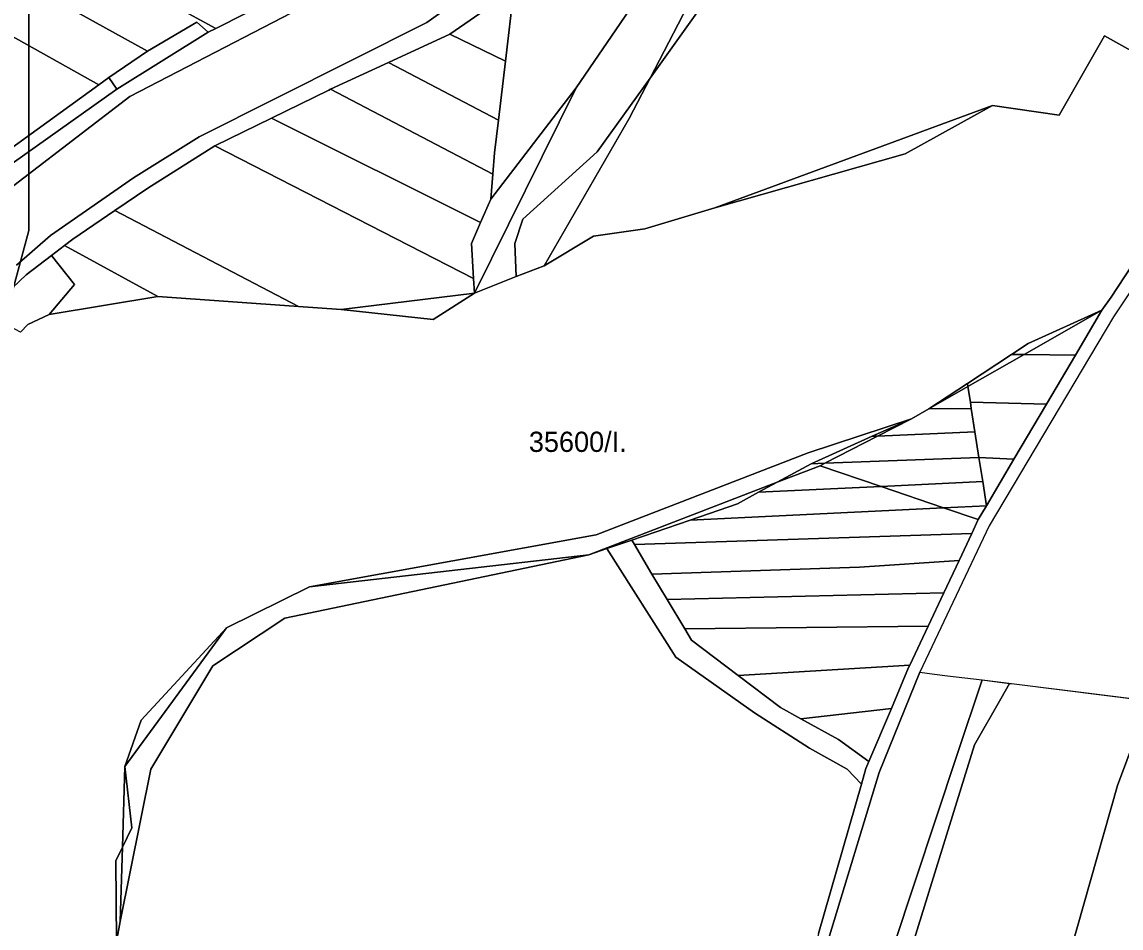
# Model space of a CAD drawing. Extents: x -537068 to -534056, y -1176840 to -1172401.
# Drawn here: x -534968.9 to -534697.4, y -1175404.2 to -1175180.5 of the extents above; entities that cross this region are included whole.
import ezdxf

# ---------------------------------------------------------------- set-up
doc = ezdxf.new("R2010")
doc.units = 0
for name, color, linetype in [('95560013', 7, 'Continuous'), ('95610013', 7, 'Continuous'), ('95630013', 7, 'Continuous'), ('95640013', 7, 'Continuous'), ('95660013', 7, 'Continuous')]:
    doc.layers.add(name, color=color, linetype=linetype)

msp = doc.modelspace()

# ---------------------------------------------------------------- linework, layer by layer
at = {"layer": '95560013'}
for points in [[(-534906.46, -1175174.67), (-534921.01, -1175182.07), (-534981.98, -1175148.9), (-535049.94, -1175112), (-535112.93, -1175078.12), (-535111.66, -1175074.89), (-535108.69, -1175067.32), (-535042.15, -1175102.18), (-534977.55, -1175137.23)], [(-535112.93, -1175078.12), (-535049.94, -1175112), (-534981.98, -1175148.9), (-534921.01, -1175182.07), (-534922.88, -1175183.02), (-534925.65, -1175180.5), (-534937.89, -1175187.69), (-535021.54, -1175141.41), (-535117.56, -1175089.94), (-535116.74, -1175087.85)], [(-535021.54, -1175141.41), (-534937.89, -1175187.69), (-534947.44, -1175194.22), (-534949.86, -1175195.98), (-535025.96, -1175153.4), (-535121.96, -1175101.18), (-535117.56, -1175089.94)], [(-535025.96, -1175153.4), (-534949.86, -1175195.98), (-534972.25, -1175212.22), (-535043.8, -1175173.13), (-535130.9, -1175126.84), (-535127.5, -1175118.23), (-535128.17, -1175112.78), (-535121.96, -1175101.18)], [(-534945.43, -1175197.06), (-534947.44, -1175194.22), (-534937.89, -1175187.69), (-534925.65, -1175180.5), (-534922.88, -1175183.02)], [(-534962.17, -1175252.75), (-534967.42, -1175255.17), (-534969.21, -1175257.08), (-534977.93, -1175252.51), (-534967.79, -1175242.94), (-534961.57, -1175238.15), (-534955.87, -1175245.29)], [(-534756.7, -1175295.18), (-534786.96, -1175296.62), (-534782.38, -1175294.15), (-534771.74, -1175290.05)], [(-534828.89, -1175312.07), (-534782.38, -1175294.15), (-534786.96, -1175296.62), (-534792.2, -1175299.46), (-534803.85, -1175303.47), (-534818.29, -1175308.43), (-534824.39, -1175310.53)], [(-534756.7, -1175295.18), (-534741.28, -1175300.44), (-534803.85, -1175303.47), (-534792.2, -1175299.46), (-534786.96, -1175296.62)], [(-534817.63, -1175309.53), (-534818.29, -1175308.43), (-534803.85, -1175303.47), (-534741.28, -1175300.44), (-534732.7, -1175303.37), (-534734.3, -1175306.78)], [(-534817.63, -1175309.53), (-534813.28, -1175316.8), (-534809.53, -1175323.06), (-534805.18, -1175330.34), (-534803.48, -1175333.17), (-534791.97, -1175341.86), (-534781.52, -1175349.75), (-534776.5, -1175352.52), (-534767.23, -1175357.62), (-534759.7, -1175363.09), (-534760.44, -1175364.83), (-534761.56, -1175368.72), (-534765.1, -1175364.97), (-534774.38, -1175359.77), (-534787.99, -1175351.11), (-534807.39, -1175337.31), (-534824.39, -1175310.53), (-534818.29, -1175308.43)], [(-534817.63, -1175309.53), (-534734.3, -1175306.78), (-534737.42, -1175313.42), (-534762.07, -1175315.14), (-534813.28, -1175316.8)], [(-534840, -1175428.9), (-534884.82, -1175421.18), (-534945.52, -1175407.54), (-534944.63, -1175402.62), (-534937.01, -1175364.95), (-534921.73, -1175339.5), (-534903.97, -1175327.66), (-534828.89, -1175312.07), (-534824.39, -1175310.53), (-534807.39, -1175337.31), (-534787.99, -1175351.11), (-534774.38, -1175359.77), (-534765.1, -1175364.97), (-534761.56, -1175368.72), (-534772.14, -1175405.55), (-534780.35, -1175439.37)], [(-534809.53, -1175323.06), (-534813.28, -1175316.8), (-534762.07, -1175315.14), (-534737.42, -1175313.42), (-534741.19, -1175321.42)], [(-534741.19, -1175321.42), (-534745.08, -1175329.69), (-534805.18, -1175330.34), (-534809.53, -1175323.06)], [(-534805.18, -1175330.34), (-534745.08, -1175329.69), (-534749.6, -1175339.29), (-534791.97, -1175341.86), (-534803.48, -1175333.17)], [(-534776.5, -1175352.52), (-534781.52, -1175349.75), (-534791.97, -1175341.86), (-534749.6, -1175339.29), (-534749.9, -1175339.92), (-534754.16, -1175349.99)], [(-534776.5, -1175352.52), (-534754.16, -1175349.99), (-534759.7, -1175363.09), (-534767.23, -1175357.62)]]:
    msp.add_lwpolyline(points, close=True, dxfattribs=at)
at = {"layer": '95610013'}
for points in [[(-534802.18, -1175178.19), (-534792.11, -1175162.32), (-534782.71, -1175140.53), (-534776.79, -1175122.8), (-534776.64, -1175118.75), (-534774.86, -1175119.44), (-534764.86, -1175120.57), (-534754.23, -1175119.31), (-534743.23, -1175116.69), (-534735.14, -1175118.41), (-534732.83, -1175122.62), (-534698.96, -1175151.8), (-534671.99, -1175175.95), (-534689.42, -1175190.63), (-534701.57, -1175183.88), (-534712.71, -1175203.47), (-534729.22, -1175201.14), (-534797.78, -1175226.37), (-534815.07, -1175231.57), (-534827.68, -1175233.4), (-534839.9, -1175240.66), (-534818.91, -1175204.32), (-534813.73, -1175194.33)], [(-534782.71, -1175140.53), (-534792.11, -1175162.32), (-534802.18, -1175178.19), (-534813.73, -1175194.33), (-534783.56, -1175136.2), (-534787.65, -1175131.83), (-534810.07, -1175164.62), (-534805.14, -1175156.04), (-534795.83, -1175136.03), (-534793.96, -1175129.55), (-534788.03, -1175123.99), (-534781.42, -1175116.91), (-534776.64, -1175118.75), (-534776.79, -1175122.8)], [(-534849.48, -1175190.2), (-534847.39, -1175172.45), (-534823.7, -1175154.79), (-534803.26, -1175138.27), (-534793.96, -1175129.55), (-534795.83, -1175136.03), (-534805.14, -1175156.04), (-534810.07, -1175164.62), (-534832, -1175196.71), (-534853.09, -1175224.2), (-534852.58, -1175218.03), (-534852.14, -1175212.78), (-534851.19, -1175204.71)], [(-534863.19, -1175183.49), (-534848.37, -1175173.18), (-534847.39, -1175172.45), (-534849.48, -1175190.2)], [(-534851.19, -1175204.71), (-534878.38, -1175190.51), (-534863.19, -1175183.49), (-534849.48, -1175190.2)], [(-534878.38, -1175190.51), (-534851.19, -1175204.71), (-534852.14, -1175212.78), (-534852.58, -1175218.03), (-534892.65, -1175197.11)], [(-534892.65, -1175197.11), (-534852.58, -1175218.03), (-534853.09, -1175224.2), (-534855.61, -1175229.99), (-534907.23, -1175204.22), (-534893.11, -1175197.32)], [(-534857.35, -1175243.8), (-534857.86, -1175235.15), (-534855.61, -1175229.99), (-534853.09, -1175224.2), (-534832, -1175196.71), (-534857.14, -1175247.43)], [(-534907.23, -1175204.22), (-534855.61, -1175229.99), (-534857.86, -1175235.15), (-534857.35, -1175243.8), (-534921.26, -1175211.07)], [(-534945.94, -1175227.05), (-534937.77, -1175221.49), (-534921.26, -1175211.07), (-534857.35, -1175243.8), (-534857.14, -1175247.43), (-534890.06, -1175251.45), (-534900.58, -1175250.72)], [(-534900.58, -1175250.72), (-534935.34, -1175248.3), (-534958.37, -1175235.69), (-534956.3, -1175234.1), (-534945.94, -1175227.05)], [(-534961.57, -1175238.15), (-534958.37, -1175235.69), (-534935.34, -1175248.3), (-534962.17, -1175252.75), (-534955.87, -1175245.29)], [(-534721.4, -1175262.62), (-534702.15, -1175251.67), (-534708.7, -1175262.76)], [(-534708.7, -1175262.76), (-534715.83, -1175274.83), (-534734.66, -1175274.39), (-534735.27, -1175270.51), (-534721.4, -1175262.62)], [(-534735.27, -1175270.51), (-534734.66, -1175274.39), (-534734.42, -1175275.9), (-534744.88, -1175275.98)], [(-534744.88, -1175275.98), (-534734.42, -1175275.9), (-534733.52, -1175281.66), (-534757.55, -1175282.74), (-534749.22, -1175278.45)], [(-534715.83, -1175274.83), (-534723.88, -1175288.45), (-534732.53, -1175288.03), (-534733.52, -1175281.66), (-534734.42, -1175275.9), (-534734.66, -1175274.39)], [(-534770.6, -1175289.46), (-534757.55, -1175282.74), (-534733.52, -1175281.66), (-534732.53, -1175288.03)], [(-534732.53, -1175288.03), (-534731.6, -1175293.99), (-534756.7, -1175295.18), (-534771.74, -1175290.05), (-534770.6, -1175289.46)], [(-534731.6, -1175293.99), (-534732.53, -1175288.03), (-534723.88, -1175288.45), (-534730.67, -1175299.94)], [(-534730.67, -1175299.94), (-534741.28, -1175300.44), (-534756.7, -1175295.18), (-534731.6, -1175293.99)], [(-534732.7, -1175303.37), (-534741.28, -1175300.44), (-534730.67, -1175299.94)]]:
    msp.add_lwpolyline(points, close=True, dxfattribs=at)
at = {"layer": '95630013'}
for points in [[(-534806.23, -1175135.89), (-534868.85, -1175180.61), (-534925.07, -1175208.86), (-534941.34, -1175219), (-534961.83, -1175233.25), (-534970.18, -1175240.52)], [(-534981.57, -1175229.02), (-534942.22, -1175198.92), (-534888.13, -1175170.79)], [(-534888.13, -1175170.79), (-534942.22, -1175198.92), (-534981.57, -1175229.02)], [(-534985.25, -1175225.31), (-534945.43, -1175197.06), (-534922.88, -1175183.02), (-534921.01, -1175182.07), (-534906.46, -1175174.67)], [(-534969.21, -1175257.08), (-534967.42, -1175255.17), (-534962.17, -1175252.75), (-534935.34, -1175248.3), (-534900.58, -1175250.72), (-534890.06, -1175251.45), (-534867.29, -1175253.98), (-534857.14, -1175247.43), (-534846.81, -1175243.37), (-534839.9, -1175240.66), (-534827.68, -1175233.4), (-534815.07, -1175231.57), (-534797.78, -1175226.37), (-534750.74, -1175213.08), (-534729.22, -1175201.14), (-534712.71, -1175203.47), (-534701.57, -1175183.88), (-534689.42, -1175190.63)], [(-534681.52, -1175220.48), (-534699.91, -1175248.4), (-534702.15, -1175251.67), (-534720.42, -1175259.89), (-534724.52, -1175262.59), (-534735.39, -1175269.74), (-534744.88, -1175275.98), (-534749.22, -1175278.45), (-534774.71, -1175286.87), (-534827.06, -1175307.09), (-534897.88, -1175319.97), (-534918.33, -1175330.08), (-534939.42, -1175352.9), (-534943.44, -1175364.36), (-534944.06, -1175384.28), (-534945.68, -1175387.59), (-534945.52, -1175407.54)]]:
    msp.add_lwpolyline(points, dxfattribs=at)
for points in [[(-534797.78, -1175226.37), (-534729.22, -1175201.14), (-534750.74, -1175213.08)], [(-534890.06, -1175251.45), (-534857.14, -1175247.43), (-534867.29, -1175253.98)], [(-534720.42, -1175259.89), (-534702.15, -1175251.67), (-534721.4, -1175262.62), (-534724.52, -1175262.59)], [(-534735.39, -1175269.74), (-534724.52, -1175262.59), (-534721.4, -1175262.62), (-534735.27, -1175270.51)], [(-534744.88, -1175275.98), (-534735.39, -1175269.74), (-534735.27, -1175270.51)], [(-534943.44, -1175364.36), (-534939.42, -1175352.9), (-534918.33, -1175330.08)], [(-534762.7, -1175447.81), (-534770.3, -1175497.78), (-534779.24, -1175489.1), (-534782.37, -1175486.06), (-534785.66, -1175482.87), (-534778.75, -1175447.45), (-534777.26, -1175439.82), (-534769.45, -1175406.16), (-534757.17, -1175365.82), (-534747.12, -1175341.05), (-534743.53, -1175341.5), (-534740.28, -1175341.9), (-534731.77, -1175342.96), (-534737.89, -1175361.35), (-534753.6, -1175408.78)], [(-534659.8, -1175351.9), (-534670.16, -1175373.86), (-534679.46, -1175398.47), (-534690.12, -1175443.5), (-534702.48, -1175507.7), (-534714.21, -1175557.48), (-534715.33, -1175562.67), (-534717.64, -1175552.34), (-534726.3, -1175540.64), (-534729.57, -1175537.45), (-534765.42, -1175502.54), (-534770.3, -1175497.78), (-534762.7, -1175447.81), (-534753.6, -1175408.78), (-534737.89, -1175361.35), (-534731.77, -1175342.96)], [(-534944.63, -1175402.62), (-534945.52, -1175407.54), (-534945.68, -1175387.59), (-534944.06, -1175384.28)]]:
    msp.add_lwpolyline(points, close=True, dxfattribs=at)
at = {"layer": '95640013'}
for points in [[(-534845.18, -1175229.15), (-534847.11, -1175235.18), (-534846.81, -1175243.37), (-534857.14, -1175247.43), (-534832, -1175196.71), (-534810.07, -1175164.62), (-534787.65, -1175131.83), (-534783.56, -1175136.2), (-534813.73, -1175194.33), (-534826.78, -1175212.58)], [(-534826.78, -1175212.58), (-534813.73, -1175194.33), (-534818.91, -1175204.32), (-534839.9, -1175240.66), (-534846.81, -1175243.37), (-534847.11, -1175235.18), (-534845.18, -1175229.15)], [(-534782.38, -1175294.15), (-534828.89, -1175312.07), (-534897.88, -1175319.97), (-534827.06, -1175307.09), (-534774.71, -1175286.87), (-534749.22, -1175278.45), (-534758.88, -1175282.8), (-534773.95, -1175289.59)], [(-534758.88, -1175282.8), (-534749.22, -1175278.45), (-534757.55, -1175282.74)], [(-534773.95, -1175289.59), (-534758.88, -1175282.8), (-534757.55, -1175282.74), (-534770.6, -1175289.46)], [(-534773.95, -1175289.59), (-534770.6, -1175289.46), (-534771.74, -1175290.05), (-534782.38, -1175294.15)], [(-534921.73, -1175339.5), (-534937.01, -1175364.95), (-534944.63, -1175402.62), (-534944.06, -1175384.28), (-534941.69, -1175379.44), (-534943.44, -1175364.36), (-534918.33, -1175330.08), (-534897.88, -1175319.97), (-534828.89, -1175312.07), (-534903.97, -1175327.66)], [(-534943.44, -1175364.36), (-534941.69, -1175379.44), (-534944.06, -1175384.28)]]:
    msp.add_lwpolyline(points, close=True, dxfattribs=at)
for points in [[(-534970.18, -1175240.52), (-534961.83, -1175233.25), (-534941.34, -1175219), (-534925.07, -1175208.86), (-534868.85, -1175180.61), (-534806.23, -1175135.89)], [(-534848.37, -1175173.18), (-534863.19, -1175183.49), (-534878.38, -1175190.51), (-534892.65, -1175197.11), (-534893.11, -1175197.32), (-534907.23, -1175204.22), (-534921.26, -1175211.07), (-534937.77, -1175221.49), (-534945.94, -1175227.05), (-534956.3, -1175234.1), (-534958.37, -1175235.69), (-534961.57, -1175238.15), (-534967.79, -1175242.94), (-534977.93, -1175252.51)], [(-534972.25, -1175212.22), (-534949.86, -1175195.98), (-534947.44, -1175194.22), (-534945.43, -1175197.06), (-534985.25, -1175225.31)], [(-534772.14, -1175405.55), (-534761.56, -1175368.72), (-534760.44, -1175364.83), (-534759.7, -1175363.09), (-534754.16, -1175349.99), (-534749.9, -1175339.92), (-534749.6, -1175339.29), (-534745.08, -1175329.69), (-534741.19, -1175321.42), (-534737.42, -1175313.42), (-534734.3, -1175306.78), (-534732.7, -1175303.37), (-534730.67, -1175299.94), (-534723.88, -1175288.45), (-534715.83, -1175274.83), (-534708.7, -1175262.76), (-534702.15, -1175251.67), (-534699.91, -1175248.4), (-534681.52, -1175220.48)], [(-534678.69, -1175222.42), (-534699.3, -1175253.32), (-534730.05, -1175304.93), (-534747.12, -1175341.05), (-534757.17, -1175365.82), (-534769.45, -1175406.16)]]:
    msp.add_lwpolyline(points, dxfattribs=at)
at = {"layer": '95660013'}
for points in [[(-534967.19, -1175149), (-534967.19, -1175232), (-534970.73, -1175245.12), (-534976.62, -1175267), (-535000, -1175297), (-535013.12, -1175310), (-535027.81, -1175332), (-535040.81, -1175369), (-535061.62, -1175447), (-535093.81, -1175518), (-535118.81, -1175559), (-535152.62, -1175594), (-535176.62, -1175633), (-535198.37, -1175673), (-535228.62, -1175707), (-535263, -1175740), (-535306.69, -1175788), (-535349.7, -1175842.01), (-535356.19, -1175850), (-535373.87, -1175869), (-535417.62, -1175929), (-535470.69, -1176000)], [(-534970.73, -1175245.12), (-534967.19, -1175232), (-534967.19, -1175149)], [(-534678.69, -1175222.42), (-534699.3, -1175253.32), (-534730.05, -1175304.93), (-534747.12, -1175341.05), (-534743.53, -1175341.5), (-534740.28, -1175341.9), (-534731.77, -1175342.96), (-534724.96, -1175343.81), (-534727.13, -1175347.6), (-534733.62, -1175359), (-534748.5, -1175407), (-534760, -1175472), (-534768.37, -1175518), (-534774.62, -1175545), (-534795, -1175600), (-534802.81, -1175620), (-534807.12, -1175643), (-534809.04, -1175661.12), (-534810.19, -1175672), (-534830.69, -1175703)], [(-534974.5, -1175861), (-534954.87, -1175834), (-534935.12, -1175803), (-534910.87, -1175788), (-534887.37, -1175775), (-534874.37, -1175760), (-534855.12, -1175736), (-534830.69, -1175703), (-534810.19, -1175672), (-534809.04, -1175661.12), (-534807.12, -1175643), (-534802.81, -1175620), (-534795, -1175600), (-534774.62, -1175545), (-534768.37, -1175518), (-534760, -1175472), (-534748.5, -1175407), (-534733.62, -1175359), (-534727.13, -1175347.6), (-534724.96, -1175343.81), (-534723.81, -1175343.95), (-534690.47, -1175348.09)], [(-534968.5, -1175938), (-534943.5, -1175896), (-534913.12, -1175855), (-534881.19, -1175814), (-534858.87, -1175788), (-534834.69, -1175764), (-534808.69, -1175731), (-534781.12, -1175692), (-534764.87, -1175664), (-534748.81, -1175628), (-534736.12, -1175589), (-534729.91, -1175563.37), (-534726.19, -1175548), (-534724.19, -1175539.37), (-534720.87, -1175525), (-534723.26, -1175503.75), (-534724.69, -1175491), (-534724.19, -1175485.37), (-534723.37, -1175476), (-534711.62, -1175416), (-534698.31, -1175369), (-534691.38, -1175350.51)], [(-534691.38, -1175350.51), (-534698.31, -1175369), (-534711.62, -1175416), (-534723.37, -1175476), (-534724.19, -1175485.37), (-534724.69, -1175491), (-534723.26, -1175503.75), (-534720.87, -1175525), (-534724.19, -1175539.37), (-534726.19, -1175548), (-534729.91, -1175563.37), (-534736.12, -1175589), (-534748.81, -1175628), (-534764.87, -1175664), (-534781.12, -1175692), (-534808.69, -1175731), (-534834.69, -1175764), (-534858.87, -1175788), (-534881.19, -1175814), (-534913.12, -1175855), (-534943.5, -1175896), (-534968.5, -1175938)]]:
    msp.add_lwpolyline(points, dxfattribs=at)

# ---------------------------------------------------------------- texts
msp.add_text('35600/I.', height=5, rotation=360, dxfattribs=at).set_placement((-534843.68, -1175286.65))

doc.saveas('drawing.dxf')
